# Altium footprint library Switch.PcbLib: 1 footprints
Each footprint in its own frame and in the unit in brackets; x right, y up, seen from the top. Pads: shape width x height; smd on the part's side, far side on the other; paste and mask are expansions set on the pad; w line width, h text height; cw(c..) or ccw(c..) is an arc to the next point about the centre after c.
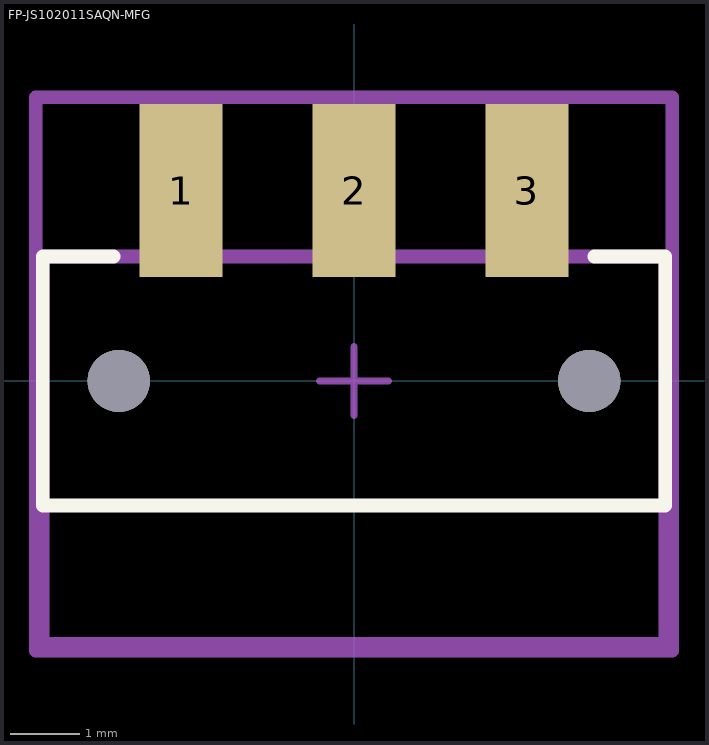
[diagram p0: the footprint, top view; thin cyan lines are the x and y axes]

## FP-JS102011SAQN-MFG [mm]
pads (5):
  rect 1.2x2.5 smd paste+0 mask+0: 1(-2.5,2.75) 2(0,2.75) 3(2.5,2.75)
  round 0.9 hole 0.9 unplated paste-2539.97 mask+0: ""(-3.4,0) ""(3.4,0)
Top Overlay:
  lines w0.2: -3.475,1.8 -4.5,1.8 -4.5,-1.8 4.5,-1.8 4.5,1.8 3.475,1.8
Top Assembly:
  lines w0.2: -4.6,-3.9 -4.6,4.1 4.6,4.1 4.6,-3.9 -4.6,-3.9
  text ".Designator" at 0,0.288 h1
Top 3D Body:
  lines w0.2: -4.5,-3.8 -4.5,1.8 4.5,1.8 4.5,-3.8 -4.5,-3.8
Top Courtyard:
  lines w0.2: -4.6,-3.9 -4.6,4.1 4.6,4.1 4.6,-3.9 -4.6,-3.9
Top Component Center:
  lines w0.1: -0.5,0 0.5,0 ; 0,-0.5 0,0.5
3D body "Switch_C&K_Components_JS102011SAQN_eec.STEP": height 0.25, standoff 0, extent -4.6,-3.9 4.6,4.1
